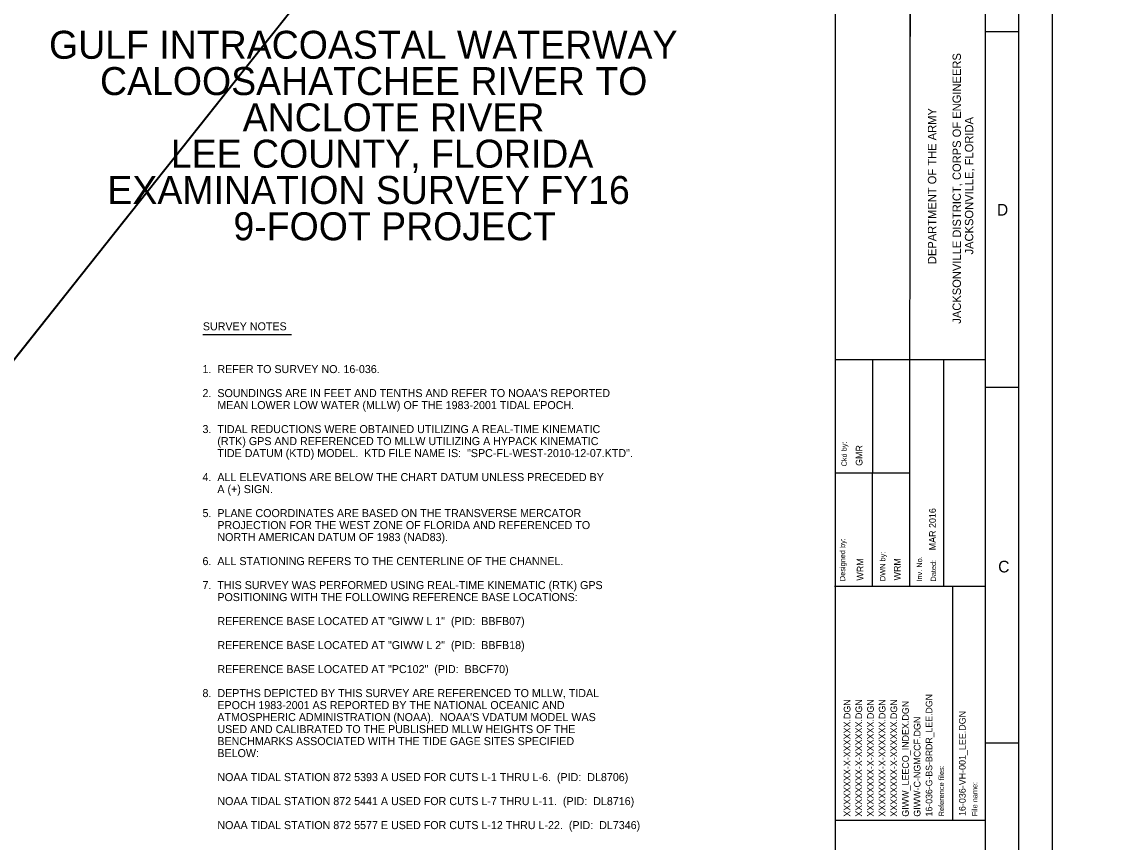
# Model space of a CAD drawing. Extents: x -42925 to 2366681, y -54064 to 2981876.
# Drawn here: x 661644 to 726584, y 804101 to 853342 of the extents above; entities that cross this region are included whole.
import ezdxf

# ---------------------------------------------------------------- set-up
doc = ezdxf.new("R2010")
doc.units = 0
for name, color, linetype in [('G-ANNO-NPLT', 7, 'Continuous'), ('G-ANNO-TEXT-DRWG', 7, 'Continuous'), ('G-ANNO-TEXT-PROJ', 7, 'Continuous'), ('G-ANNO-TEXT-TTLB', 7, 'Continuous'), ('G-ANNO-TTLB', 7, 'Continuous'), ('V-ANNO-SYMB', 7, 'Continuous'), ('V-ANNO-TEXT', 7, 'Continuous')]:
    doc.layers.add(name, color=color, linetype=linetype)

msp = doc.modelspace()

# ---------------------------------------------------------------- linework, layer by layer
at = {"layer": 'G-ANNO-NPLT'}
msp.add_lwpolyline([(547448, 899395), (723447, 899395), (723447, 763396), (547448, 763396)], close=True, dxfattribs=at)
at = {"layer": 'G-ANNO-TTLB'}
for p, q in [((710446, 895395), (710446, 767396)), ((714920, 819482), (714947, 853865)), ((714947, 853865), (714946, 852448)), ((721447, 852724), (719447, 852724)), ((710415, 833069), (719447, 833069)), ((712682, 819484), (712693, 833069)), ((716928, 833069), (716928, 819482)), ((721447, 831392), (719447, 831392)), ((710415, 826275), (714925, 826275)), ((710398, 819482), (719447, 819482)), ((717475, 819482), (717475, 805427)), ((721447, 810060), (719447, 810060)), ((710446, 805427), (719447, 805427))]:
    msp.add_line(p, q, dxfattribs=at)
for points in [[(549448, 765396), (721447, 765396), (721447, 897395), (549448, 897395)], [(719447, 895395), (554448, 895395), (554448, 767396), (719447, 767396)]]:
    msp.add_lwpolyline(points, close=True, dxfattribs=at)
at = {"layer": 'V-ANNO-SYMB'}
msp.add_spline([(691625, 871432), (691632, 871429), (691632, 871429), (691629, 871411), (691629, 871389), (691632, 871357)], degree=3, dxfattribs=at)
at = {"layer": 'V-ANNO-TEXT'}
msp.add_line((672514, 834573), (677828, 834573), dxfattribs=at)

# ---------------------------------------------------------------- texts
at = {"layer": 'G-ANNO-TEXT-DRWG'}
for s, p in [('GMR', (712076, 826688)), ('WRM', (712136, 819805)), ('WRM', (714362, 819815)), ('XXXXXXXX-X-XXXXXX.DGN', (711357, 805641)), ('XXXXXXXX-X-XXXXXX.DGN', (712057, 805641)), ('XXXXXXXX-X-XXXXXX.DGN', (712757, 805641)), ('XXXXXXXX-X-XXXXXX.DGN', (713457, 805641)), ('XXXXXXXX-X-XXXXXX.DGN', (714157, 805641)), ('GIWW_LEECO_INDEX.DGN', (714857, 805641)), ('16-036-VH-001_LEE.DGN', (718264, 805682)), ('GIWW-C-NGMCCF.DGN', (715557, 805641))]:
    msp.add_text(s, height=400, rotation=90, dxfattribs=at).set_placement(p)
at = {"layer": 'G-ANNO-TEXT-PROJ'}
for s, height, p in [('MAR 2016', 400, (716476, 821625)), ('16-036-G-BS-BRDR_LEE.DGN', 392, (716264, 805657))]:
    msp.add_text(s, height=height, rotation=90, dxfattribs=at).set_placement(p)
at = {"layer": 'G-ANNO-TEXT-TTLB'}
for s, height, p in [('JACKSONVILLE DISTRICT, CORPS OF ENGINEERS', 500, (717981, 835217)), ('DEPARTMENT OF THE ARMY', 500, (716501, 838793)), ('JACKSONVILLE, FLORIDA', 500, (718721, 839371)), ('Ckd by:', 320, (711137, 826655)), ('Designed by:', 320, (711039, 819773)), ('DWN by:', 320, (713448, 819774)), ('Inv. No.', 320, (715656, 819745)), ('Dated:', 320, (716489, 819748)), ('Reference files:', 320, (716971, 805660)), ('File name:', 320, (718970, 805669))]:
    msp.add_text(s, height=height, rotation=90, dxfattribs=at).set_placement(p)
at = {"layer": 'G-ANNO-TTLB'}
for s, p in [('D', (720140, 841705)), ('C', (720216, 820295))]:
    msp.add_text(s, height=700, dxfattribs=at).set_placement(p)
at = {"layer": 'V-ANNO-TEXT'}
for s, height, p in [('GULF INTRACOASTAL WATERWAY', 1680, (663287, 851114)), ('CALOOSAHATCHEE RIVER TO', 1680, (666344, 848936)), ('ANCLOTE RIVER', 1680, (674900, 846758)), ('LEE COUNTY, FLORIDA', 1680, (670593, 844580)), ('EXAMINATION SURVEY FY16', 1680, (666788, 842402)), ('9-FOOT PROJECT', 1680, (674346, 840224)), ('SURVEY NOTES', 480, (672513, 834821)), ('1.  REFER TO SURVEY NO. 16-036.', 480, (672491, 832256)), ("2.  SOUNDINGS ARE IN FEET AND TENTHS AND REFER TO NOAA'S REPORTED", 480, (672491, 830816)), ('     MEAN LOWER LOW WATER (MLLW) OF THE 1983-2001 TIDAL EPOCH.', 480, (672491, 830096)), ('3.  TIDAL REDUCTIONS WERE OBTAINED UTILIZING A REAL-TIME KINEMATIC', 480, (672491, 828656)), ('     (RTK) GPS AND REFERENCED TO MLLW UTILIZING A HYPACK KINEMATIC', 480, (672491, 827936)), ('     TIDE DATUM (KTD) MODEL.  KTD FILE NAME IS:  "SPC-FL-WEST-2010-12-07.KTD".', 480, (672491, 827216)), ('4.  ALL ELEVATIONS ARE BELOW THE CHART DATUM UNLESS PRECEDED BY', 480, (672491, 825776)), ('     A (+) SIGN.', 480, (672491, 825056)), ('5.  PLANE COORDINATES ARE BASED ON THE TRANSVERSE MERCATOR', 480, (672491, 823616)), ('     PROJECTION FOR THE WEST ZONE OF FLORIDA AND REFERENCED TO', 480, (672491, 822896)), ('     NORTH AMERICAN DATUM OF 1983 (NAD83).', 480, (672491, 822176)), ('6.  ALL STATIONING REFERS TO THE CENTERLINE OF THE CHANNEL.', 480, (672491, 820736)), ('7.  THIS SURVEY WAS PERFORMED USING REAL-TIME KINEMATIC (RTK) GPS', 480, (672491, 819296)), ('     POSITIONING WITH THE FOLLOWING REFERENCE BASE LOCATIONS:', 480, (672491, 818576)), ('     REFERENCE BASE LOCATED AT "GIWW L 1"  (PID:  BBFB07)', 480, (672491, 817136)), ('     REFERENCE BASE LOCATED AT "GIWW L 2"  (PID:  BBFB18)', 480, (672491, 815696)), ('     REFERENCE BASE LOCATED AT "PC102"  (PID:  BBCF70)', 480, (672491, 814256)), ('8.  DEPTHS DEPICTED BY THIS SURVEY ARE REFERENCED TO MLLW, TIDAL', 480, (672491, 812816)), ('     EPOCH 1983-2001 AS REPORTED BY THE NATIONAL OCEANIC AND', 480, (672491, 812096)), ("     ATMOSPHERIC ADMINISTRATION (NOAA).  NOAA'S VDATUM MODEL WAS", 480, (672491, 811376)), ('     USED AND CALIBRATED TO THE PUBLISHED MLLW HEIGHTS OF THE ', 480, (672491, 810656)), ('     BENCHMARKS ASSOCIATED WITH THE TIDE GAGE SITES SPECIFIED', 480, (672491, 809936)), ('     BELOW:', 480, (672491, 809216)), ('     NOAA TIDAL STATION 872 5393 A USED FOR CUTS L-1 THRU L-6.  (PID:  DL8706)', 480, (672491, 807776)), ('     NOAA TIDAL STATION 872 5441 A USED FOR CUTS L-7 THRU L-11.  (PID:  DL8716)', 480, (672491, 806336)), ('     NOAA TIDAL STATION 872 5577 E USED FOR CUTS L-12 THRU L-22.  (PID:  DL7346) ', 480, (672491, 804896))]:
    msp.add_text(s, height=height, dxfattribs=at).set_placement(p)

doc.saveas('drawing.dxf')
